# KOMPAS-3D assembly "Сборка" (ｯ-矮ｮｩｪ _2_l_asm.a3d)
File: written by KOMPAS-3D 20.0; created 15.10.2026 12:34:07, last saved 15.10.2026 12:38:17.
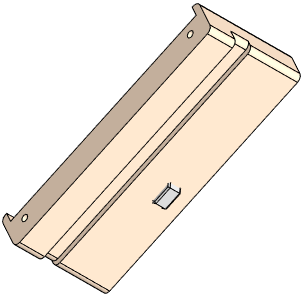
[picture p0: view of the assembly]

Document properties: Полное имя файла: D:\RicWork\Project-EPS32\box_compas\корпус\п-стойка_2_l_asm.a3d

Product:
- Part/product: Сборка
    Масса: 0.0264411
  - Component [detail]: Деталь  | Масса: 0.000354634; source file: ..\прочее\гайка_м3.m3d
  - Component [detail]: Деталь  | Масса: 0.0260865; source file: п-стойка_2_l.m3d

Referenced files in D:\RicWork\Project-EPS32\box_compas\корпус\: п-стойка_2_l.m3d
Referenced files in D:\RicWork\Project-EPS32\box_compas\прочее\: гайка_м3.m3d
